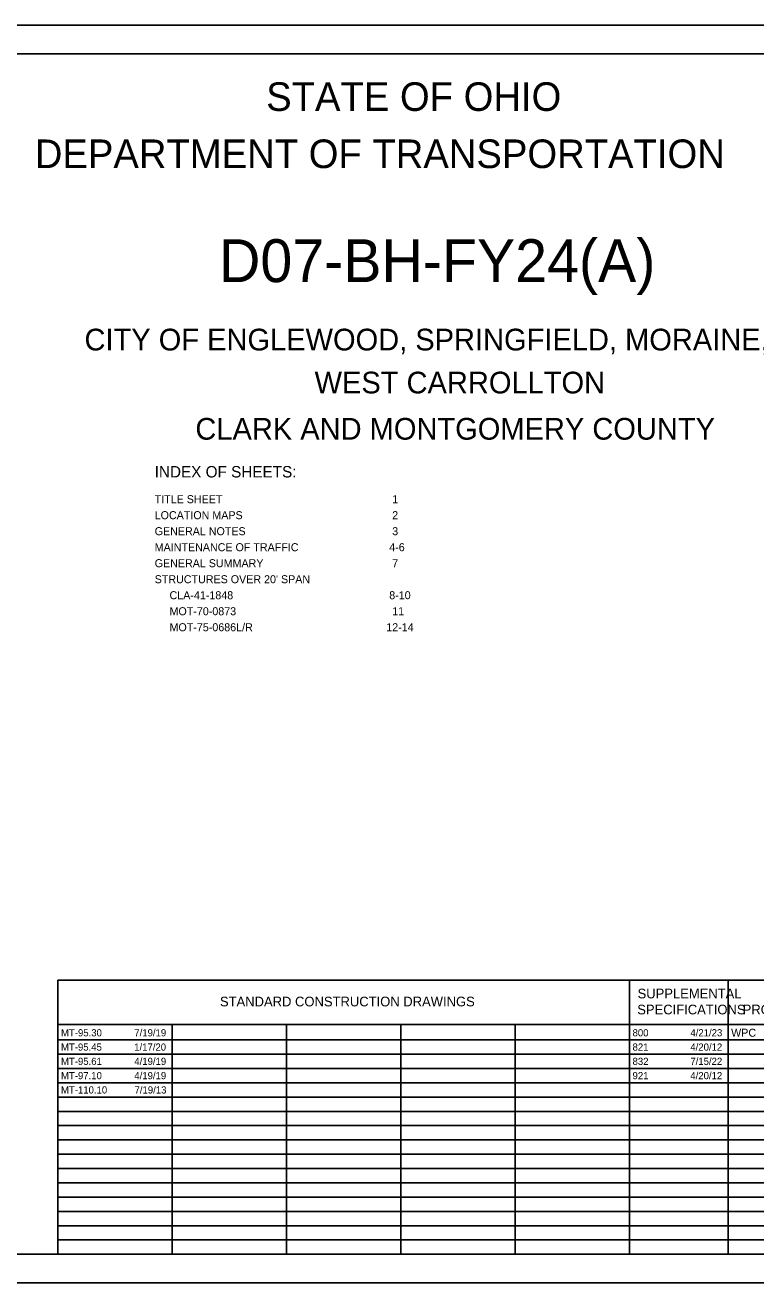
# Model space of a CAD drawing. Extents: x -31.7 to 34, y 0 to 22.
# Drawn here: x 9.58 to 22.36, y 0 to 22 of the extents above; entities that cross this region are included whole.
import ezdxf

# ---------------------------------------------------------------- set-up
doc = ezdxf.new("R2010")
doc.units = 0
for name, color, linetype in [('SH_Border', 7, 'Continuous'), ('SH_Cut_Line', 7, 'Continuous'), ('SH_Data', 7, 'Continuous'), ('SH_Text', 7, 'Continuous')]:
    doc.layers.add(name, color=color, linetype=linetype)

msp = doc.modelspace()

# ---------------------------------------------------------------- linework, layer by layer
at = {"layer": 'SH_Border'}
msp.add_lwpolyline([(1.5, 21.5), (33.5, 21.5), (33.5, 0.5), (1.5, 0.5)], close=True, dxfattribs=at)
at = {"layer": 'SH_Cut_Line'}
msp.add_lwpolyline([(0, 0), (34, 0), (34, 22), (0, 22)], close=True, dxfattribs=at)
at = {"layer": 'SH_Data'}
for p, q in [((10.15, 5.292), (23.6, 5.292)), ((10.15, 0.5), (10.15, 5.292)), ((20.15, 0.5), (20.15, 5.292)), ((21.875, 0.5), (21.875, 5.292)), ((10.15, 4.521), (23.6, 4.521)), ((12.15, 0.5), (12.15, 4.521)), ((14.15, 0.5), (14.15, 4.521)), ((16.15, 0.5), (16.15, 4.521)), ((18.15, 0.5), (18.15, 4.521)), ((10.15, 4.25), (23.6, 4.25)), ((10.15, 4), (23.6, 4)), ((10.15, 3.75), (23.6, 3.75)), ((10.15, 3.5), (23.6, 3.5)), ((10.15, 3.25), (23.6, 3.25)), ((10.15, 3), (23.6, 3)), ((10.15, 2.75), (23.6, 2.75)), ((10.15, 2.5), (23.6, 2.5)), ((10.15, 2.25), (23.6, 2.25)), ((10.15, 2), (23.6, 2)), ((10.15, 1.75), (23.6, 1.75)), ((10.15, 1.5), (23.6, 1.5)), ((10.15, 1.25), (23.6, 1.25)), ((10.15, 1), (23.6, 1)), ((10.15, 0.75), (23.6, 0.75))]:
    msp.add_line(p, q, dxfattribs=at)

# ---------------------------------------------------------------- texts
at = {"layer": 'SH_Text'}
for s, height, p in [('STATE OF OHIO', 0.5, (13.795, 20.5)), ('DEPARTMENT OF TRANSPORTATION', 0.5, (9.747, 19.5)), ('D07-BH-FY24(A)', 0.75, (12.969, 17.505)), ('CITY OF ENGLEWOOD, SPRINGFIELD, MORAINE, AND', 0.38, (10.616, 16.31)), ('WEST CARROLLTON', 0.38, (14.642, 15.558)), ('CLARK AND MONTGOMERY COUNTY', 0.38, (12.556, 14.749)), ('INDEX OF SHEETS:', 0.2, (11.844, 14.088)), ('TITLE SHEET                         ', 0.14, (11.844, 13.638)), ('   1   ', 0.14, (15.844, 13.638)), ('LOCATION MAPS                       ', 0.14, (11.844, 13.358)), ('   2   ', 0.14, (15.844, 13.358)), ('GENERAL NOTES                       ', 0.14, (11.844, 13.078)), ('   3   ', 0.14, (15.844, 13.078)), ('MAINTENANCE OF TRAFFIC              ', 0.14, (11.844, 12.798)), ('  4-6  ', 0.14, (15.844, 12.798)), ('GENERAL SUMMARY                     ', 0.14, (11.844, 12.518)), ('   7   ', 0.14, (15.844, 12.518)), ("STRUCTURES OVER 20' SPAN            ", 0.14, (11.844, 12.238)), ('     CLA-41-1848                    ', 0.14, (11.844, 11.958)), ('  8-10 ', 0.14, (15.844, 11.958)), ('     MOT-70-0873                    ', 0.14, (11.844, 11.678)), ('   11  ', 0.14, (15.844, 11.678)), ('     MOT-75-0686L/R                 ', 0.14, (11.844, 11.398)), (' 12-14 ', 0.14, (15.844, 11.398)), ('SUPPLEMENTAL', 0.17, (20.293, 4.976)), ('STANDARD CONSTRUCTION DRAWINGS', 0.17, (12.986, 4.836)), ('SPECIFICATIONS', 0.17, (20.287, 4.696)), ('PROVISIONS', 0.17, (22.132, 4.696)), ('MT-95.30', 0.125, (10.205, 4.312)), ('7/19/19', 0.125, (11.488, 4.312)), ('800', 0.125, (20.205, 4.312)), ('4/21/23', 0.125, (21.217, 4.312)), ('WPC', 0.14, (21.93, 4.305)), ('MT-95.45', 0.125, (10.205, 4.062)), ('1/17/20', 0.125, (11.486, 4.062)), ('821', 0.125, (20.205, 4.062)), ('4/20/12', 0.125, (21.216, 4.062)), ('MT-95.61', 0.125, (10.205, 3.812)), ('4/19/19', 0.125, (11.488, 3.812)), ('832', 0.125, (20.205, 3.812)), ('7/15/22', 0.125, (21.216, 3.812)), ('MT-97.10', 0.125, (10.205, 3.562)), ('4/19/19', 0.125, (11.488, 3.562)), ('921', 0.125, (20.205, 3.562)), ('4/20/12', 0.125, (21.216, 3.562)), ('MT-110.10', 0.125, (10.205, 3.312)), ('7/19/13', 0.125, (11.492, 3.312))]:
    msp.add_text(s, height=height, dxfattribs=at).set_placement(p)

doc.saveas('drawing.dxf')
